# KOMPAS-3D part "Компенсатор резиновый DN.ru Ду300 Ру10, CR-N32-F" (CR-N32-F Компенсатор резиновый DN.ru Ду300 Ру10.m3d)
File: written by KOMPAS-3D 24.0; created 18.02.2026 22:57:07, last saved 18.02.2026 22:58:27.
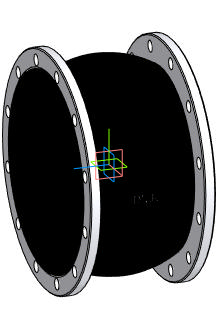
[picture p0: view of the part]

Document properties: Автор: DN.RU; Полное имя файла: D:\PROJECT CAD\DN.RU\...178(2)(ACTUALE). CR-N32-F Компенсатор резиновый DN.ru Ру10-16\CR-N32-F Компенсатор резиновый DN.ru Ру10-16\DN300_PN10\CR-N32-F Компенсатор резиновый DN.ru Ду300 Ру10.m3d

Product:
- Body: Твердое тело2  | qty 1
    Масса: 94.24882
- Part/product: Компенсатор резиновый DN.ru Ду300 Ру10  | designation CR-N32-F
    Масса: 30
    Раздел спецификации: Прочие изделия
    Комментарий: D140-02399
    Примечание: D140-02384
    additional columns: Типовые

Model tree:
1. Твердое тело2  (labels: Твердое тело2)

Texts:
  CR-N32-F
